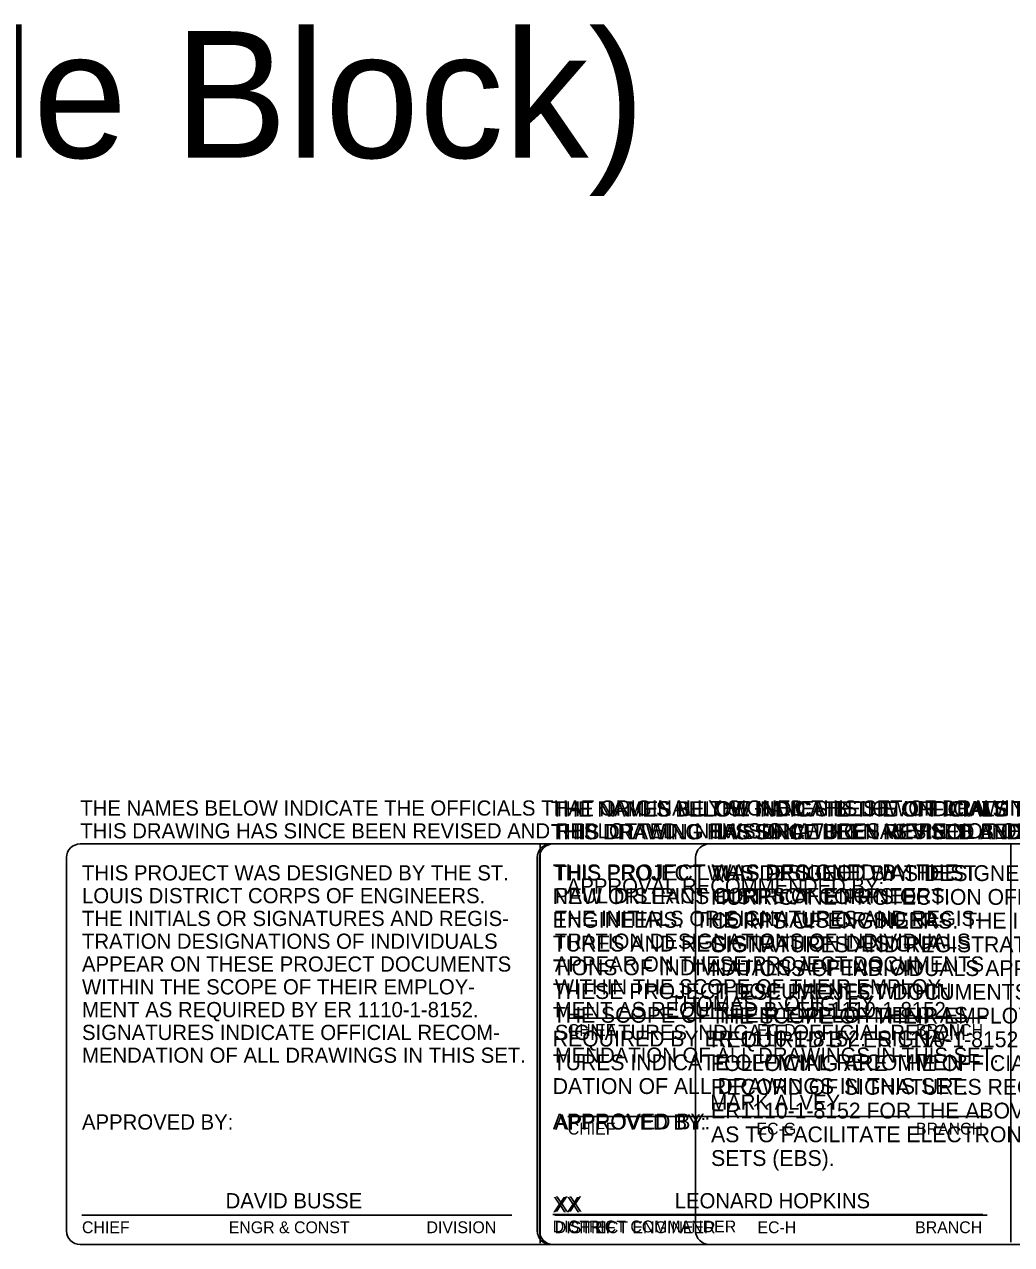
# Model space of a CAD drawing. Extents: x 0 to 2.77, y 0 to 1.73.
# Drawn here: x 1.318 to 1.967, y 0.069 to 0.872 of the extents above; entities that cross this region are included whole.
import ezdxf

# ---------------------------------------------------------------- set-up
doc = ezdxf.new("R2010")
doc.units = 0
for name, color, linetype in [('G-ANNO-TEXT-HPOA', 7, 'Continuous'), ('G-ANNO-TEXT-HPOS', 7, 'Continuous'), ('G-ANNO-TEXT-MVNA', 7, 'Continuous'), ('G-ANNO-TEXT-MVNS', 7, 'Continuous'), ('G-ANNO-TEXT-MVPA', 7, 'Continuous'), ('G-ANNO-TEXT-MVPS', 7, 'Continuous'), ('G-ANNO-TEXT-MVSA', 7, 'Continuous'), ('G-ANNO-TEXT-MVSS', 7, 'Continuous'), ('G-ANNO-TEXT-PROJ', 7, 'Continuous')]:
    doc.layers.add(name, color=color, linetype=linetype)

msp = doc.modelspace()

# ---------------------------------------------------------------- linework, layer by layer
at = {"layer": 'G-ANNO-TEXT-HPOS'}
for p, q in [((1.76837, 0.33296), (2.58269, 0.33296)), ((1.76837, 0.33296), (2.58269, 0.33296)), ((1.75936, 0.2753), (1.75937, 0.32396)), ((1.75936, 0.2753), (1.75937, 0.32396)), ((1.75937, 0.07829), (1.75936, 0.2753)), ((1.75937, 0.07829), (1.75936, 0.2753)), ((2.58269, 0.0693), (1.76837, 0.06929)), ((2.58269, 0.0693), (1.76837, 0.06929))]:
    msp.add_line(p, q, dxfattribs=at)
for centre, start, end in [((1.76837, 0.32396), 90.00016, 179.99568), ((1.76837, 0.32396), 90.00016, 179.99568), ((1.76837, 0.07829), 180.00121, 270.00016), ((1.76837, 0.07829), 180.00121, 270.00016)]:
    msp.add_arc(centre, 0.009, start, end, dxfattribs=at)
at = {"layer": 'G-ANNO-TEXT-MVNS'}
for p, q in [((1.6642, 0.33297), (2.58269, 0.33297)), ((1.6552, 0.27581), (1.6552, 0.32397)), ((1.6552, 0.07831), (1.6552, 0.27581)), ((1.94821, 0.08914), (1.66536, 0.08914)), ((2.58269, 0.0693), (1.6642, 0.06931))]:
    msp.add_line(p, q, dxfattribs=at)
msp.add_lwpolyline([(1.9667, 0.33347), (1.9667, 0.07081)], dxfattribs=at)
for centre, start, end in [((1.6642, 0.32397), 89.99971, 179.99632), ((1.6642, 0.07831), 180.00102, 269.99971)]:
    msp.add_arc(centre, 0.009, start, end, dxfattribs=at)
at = {"layer": 'G-ANNO-TEXT-MVPS'}
for p, q in [((1.66561, 0.33297), (2.58269, 0.33297)), ((1.65661, 0.0783), (1.6566, 0.32397)), ((1.6566, 0.32397), (1.65661, 0.32397)), ((1.94961, 0.08864), (1.66677, 0.08864)), ((2.58269, 0.0693), (1.66561, 0.0693))]:
    msp.add_line(p, q, dxfattribs=at)
for centre, start, end in [((1.66561, 0.32396), 90.0001, 179.99303), ((1.66561, 0.0783), 180.00195, 270.0001)]:
    msp.add_arc(centre, 0.009, start, end, dxfattribs=at)
at = {"layer": 'G-ANNO-TEXT-MVSS'}
for p, q in [((1.35453, 0.33296), (2.58269, 0.33296)), ((1.34553, 0.07829), (1.34553, 0.32396)), ((1.34553, 0.32396), (1.34553, 0.32396)), ((1.95081, 0.21841), (1.6753, 0.21841)), ((1.9508, 0.15352), (1.67529, 0.15352)), ((1.63854, 0.08863), (1.3557, 0.08863)), ((1.95113, 0.08863), (1.67529, 0.08863)), ((2.58269, 0.0693), (1.35453, 0.06929))]:
    msp.add_line(p, q, dxfattribs=at)
msp.add_lwpolyline([(1.65703, 0.33296), (1.65703, 0.0703)], dxfattribs=at)
for centre, start, end in [((1.35453, 0.32396), 90.00008, 179.99568), ((1.35453, 0.07829), 180.00121, 270.00008)]:
    msp.add_arc(centre, 0.009, start, end, dxfattribs=at)

# ---------------------------------------------------------------- texts
at = {"layer": 'G-ANNO-TEXT-HPOA'}
for s, p in [('THE NAMES BELOW INDICATE THE OFFICIALS THAT ORIGINALLY SIGNED THIS SET OF DRAWINGS.', (1.76838, 0.35123)), ('THIS DRAWING HAS SINCE BEEN REVISED AND REPLOTTED.  NEW SIGNATURES WERE NOT OBTAINED.', (1.76838, 0.33623))]:
    msp.add_text(s, height=0.01, rotation=360, dxfattribs=at).set_placement(p)
at = {"layer": 'G-ANNO-TEXT-HPOS'}
for s, p in [('THIS PROJECT WAS DESIGNED BY THE ', (1.76952, 0.30853)), ('THIS PROJECT WAS DESIGNED BY THE ', (1.76952, 0.30853)), ('HURRICANE PROTECTION OFFICE, ', (1.76952, 0.2929)), ('HURRICANE PROTECTION OFFICE, ', (1.76952, 0.2929)), ('CORPS OF ENGINEERS. THE INITIALS OR ', (1.76952, 0.27728)), ('CORPS OF ENGINEERS. THE INITIALS OR ', (1.76952, 0.27728)), ('SIGNATURES AND REGISTRATION DESIG-', (1.76952, 0.26165)), ('SIGNATURES AND REGISTRATION DESIG-', (1.76952, 0.26165)), ('NATIONS OF INDIVIDUALS APPEAR ON ', (1.76952, 0.24603)), ('NATIONS OF INDIVIDUALS APPEAR ON ', (1.76952, 0.24603)), ('THESE PROJECT DOCUMENTS WITHIN ', (1.76952, 0.2304)), ('THESE PROJECT DOCUMENTS WITHIN ', (1.76952, 0.2304)), ('THE SCOPE OF THEIR EMPLOYMENT AS ', (1.76952, 0.21478)), ('THE SCOPE OF THEIR EMPLOYMENT AS ', (1.76952, 0.21478)), ('REQUIRED BY ER 1110-1-8152.  THE ', (1.76952, 0.19915)), ('REQUIRED BY ER 1110-1-8152.  THE ', (1.76952, 0.19915)), ('FOLLOWING ARE THE OFFICIAL WRITTEN ', (1.76952, 0.18353)), ('FOLLOWING ARE THE OFFICIAL WRITTEN ', (1.76952, 0.18353)), ('RECORD OF SIGNATURES REQUIRED BY', (1.76952, 0.1679)), ('RECORD OF SIGNATURES REQUIRED BY', (1.76952, 0.1679)), ('ER1110-1-8152 FOR THE ABOVE JOB SO ', (1.76952, 0.15228)), ('ER1110-1-8152 FOR THE ABOVE JOB SO ', (1.76952, 0.15228)), ('AS TO FACILITATE ELECTRONIC BID ', (1.76952, 0.13665)), ('AS TO FACILITATE ELECTRONIC BID ', (1.76952, 0.13665)), ('SETS (EBS).', (1.76952, 0.12103)), ('SETS (EBS).', (1.76952, 0.12103))]:
    msp.add_text(s, height=0.0104167, rotation=360, dxfattribs=at).set_placement(p)
at = {"layer": 'G-ANNO-TEXT-MVNA'}
for s, p in [('THE NAMES BELOW INDICATE THE OFFICIALS THAT ORIGINALLY SIGNED THIS SET OF DRAWINGS.', (1.6642, 0.35098)), ('THIS DRAWING HAS SINCE BEEN REVISED AND REPLOTTED.  NEW SIGNATURES WERE NOT OBTAINED.', (1.6642, 0.33598)), ('XX', (1.66536, 0.09063))]:
    msp.add_text(s, height=0.01, rotation=360, dxfattribs=at).set_placement(p)
at = {"layer": 'G-ANNO-TEXT-MVNS'}
for s, height, p in [('THIS PROJECT WAS DESIGNED BY THE ', 0.0104167, (1.66535, 0.30904)), ('NEW ORLEANS DISTRICT CORPS OF ', 0.0104167, (1.66535, 0.29341)), ('ENGINEERS.  THE INITIALS OR SIGNA-', 0.0104167, (1.66535, 0.27779)), ('TURES AND REGISTRATION DESIGNA-', 0.0104167, (1.66535, 0.26216)), ('TIONS OF INDIVIDUALS APPEAR ON ', 0.0104167, (1.66535, 0.24654)), ('THESE PROJECT DOCUMENTS WITHIN', 0.0104167, (1.66535, 0.23091)), ('THE SCOPE OF THEIR EMPLOYMENT AS ', 0.0104167, (1.66535, 0.21529)), ('REQUIRED BY ER 1110-1-8152.  SIGNA-', 0.0104167, (1.66535, 0.19966)), ('TURES INDICATE OFFICIAL RECOMMEN-', 0.0104167, (1.66535, 0.18404)), ('DATION OF ALL DRAWINGS IN THIS SET.', 0.0104167, (1.66535, 0.16841)), ('APPROVED BY:', 0.0104167, (1.66534, 0.14508)), ('DISTRICT COMMANDER', 0.0078125, (1.66534, 0.07731))]:
    msp.add_text(s, height=height, rotation=360, dxfattribs=at).set_placement(p)
at = {"layer": 'G-ANNO-TEXT-MVPA'}
for s, p in [('THE NAMES BELOW INDICATE THE OFFICIALS THAT ORIGINALLY SIGNED THIS SET OF DRAWINGS.', (1.66563, 0.35104)), ('THIS DRAWING HAS SINCE BEEN REVISED AND REPLOTTED.  NEW SIGNATURES WERE NOT OBTAINED.', (1.66563, 0.33604)), ('XX', (1.66679, 0.09098))]:
    msp.add_text(s, height=0.01, rotation=360, dxfattribs=at).set_placement(p)
at = {"layer": 'G-ANNO-TEXT-MVPS'}
for s, height, p in [('THIS PROJECT WAS DESIGNED BY THE ST.', 0.01, (1.66676, 0.30895)), ('PAUL DISTRICT CORPS OF ENGINEERS.  ', 0.01, (1.66676, 0.29395)), ('THE INITIALS OR SIGNATURES AND REGIS-', 0.01, (1.66676, 0.27895)), ('TRATION DESIGNATIONS OF INDIVIDUALS', 0.01, (1.66676, 0.26395)), ('APPEAR ON THESE PROJECT DOCUMENTS', 0.01, (1.66676, 0.24895)), ('WITHIN THE SCOPE OF THEIR EMPLOY-', 0.01, (1.66676, 0.23395)), ('MENT AS REQUIRED BY ER 1110-1-8152.  ', 0.01, (1.66676, 0.21895)), ('SIGNATURES INDICATE OFFICIAL RECOM-', 0.01, (1.66676, 0.20395)), ('MENDATION OF ALL DRAWINGS IN THIS SET.', 0.01, (1.66676, 0.18895)), ('APPROVED BY:', 0.01, (1.66675, 0.14499)), ('DISTRICT ENGINEER', 0.0078125, (1.66675, 0.0768))]:
    msp.add_text(s, height=height, rotation=360, dxfattribs=at).set_placement(p)
at = {"layer": 'G-ANNO-TEXT-MVSA'}
for s, p in [('THE NAMES BELOW INDICATE THE OFFICIALS THAT ORIGINALLY SIGNED THIS SET OF DRAWINGS.  ', (1.35455, 0.3516)), ('THIS DRAWING HAS SINCE BEEN REVISED AND REPLOTTED.  NEW SIGNATURES WERE NOT OBTAINED.', (1.35455, 0.3366)), ('THOMAS J. QUIGLEY', (1.74246, 0.22294)), ('MARK ALVEY', (1.76897, 0.15805)), ('DAVID BUSSE', (1.45016, 0.09316)), ('LEONARD HOPKINS', (1.74555, 0.09316))]:
    msp.add_text(s, height=0.01, rotation=360, dxfattribs=at).set_placement(p)
at = {"layer": 'G-ANNO-TEXT-MVSS'}
for s, height, p in [('THIS PROJECT WAS DESIGNED BY THE ST. ', 0.01, (1.35569, 0.30894)), ('APPROVAL RECOMMENDED BY:', 0.01, (1.67461, 0.30028)), ('LOUIS DISTRICT CORPS OF ENGINEERS.  ', 0.01, (1.35569, 0.29394)), ('THE INITIALS OR SIGNATURES AND REGIS-', 0.01, (1.35569, 0.27894)), ('TRATION DESIGNATIONS OF INDIVIDUALS ', 0.01, (1.35569, 0.26394)), ('APPEAR ON THESE PROJECT DOCUMENTS ', 0.01, (1.35569, 0.24894)), ('WITHIN THE SCOPE OF THEIR EMPLOY-', 0.01, (1.35569, 0.23394)), ('MENT AS REQUIRED BY ER 1110-1-8152.  ', 0.01, (1.35569, 0.21894)), ('SIGNATURES INDICATE OFFICIAL RECOM-', 0.01, (1.35569, 0.20394)), ('CHIEF', 0.007812, (1.67529, 0.20658)), ('EC-D', 0.007812, (1.79971, 0.20657)), ('BRANCH', 0.007812, (1.90429, 0.20658)), ('MENDATION OF ALL DRAWINGS IN THIS SET.', 0.01, (1.35569, 0.18894)), ('APPROVED BY:', 0.01, (1.35568, 0.14499)), ('CHIEF', 0.007812, (1.67528, 0.14169)), ('EC-G', 0.007812, (1.79937, 0.14168)), ('BRANCH', 0.007812, (1.90428, 0.14169)), ('CHIEF', 0.007812, (1.35569, 0.0768)), ('ENGR & CONST', 0.0078125, (1.45222, 0.07679)), ('DIVISION', 0.007812, (1.58233, 0.0768)), ('CHIEF', 0.007812, (1.67528, 0.0768)), ('EC-H', 0.007812, (1.80002, 0.07679)), ('BRANCH', 0.007812, (1.90374, 0.0768))]:
    msp.add_text(s, height=height, rotation=360, dxfattribs=at).set_placement(p)
at = {"layer": 'G-ANNO-TEXT-PROJ'}
msp.add_text('Project Title (as in Title Block)', height=0.0833333, dxfattribs=at).set_placement((0.25219, 0.78451))

doc.saveas('drawing.dxf')
